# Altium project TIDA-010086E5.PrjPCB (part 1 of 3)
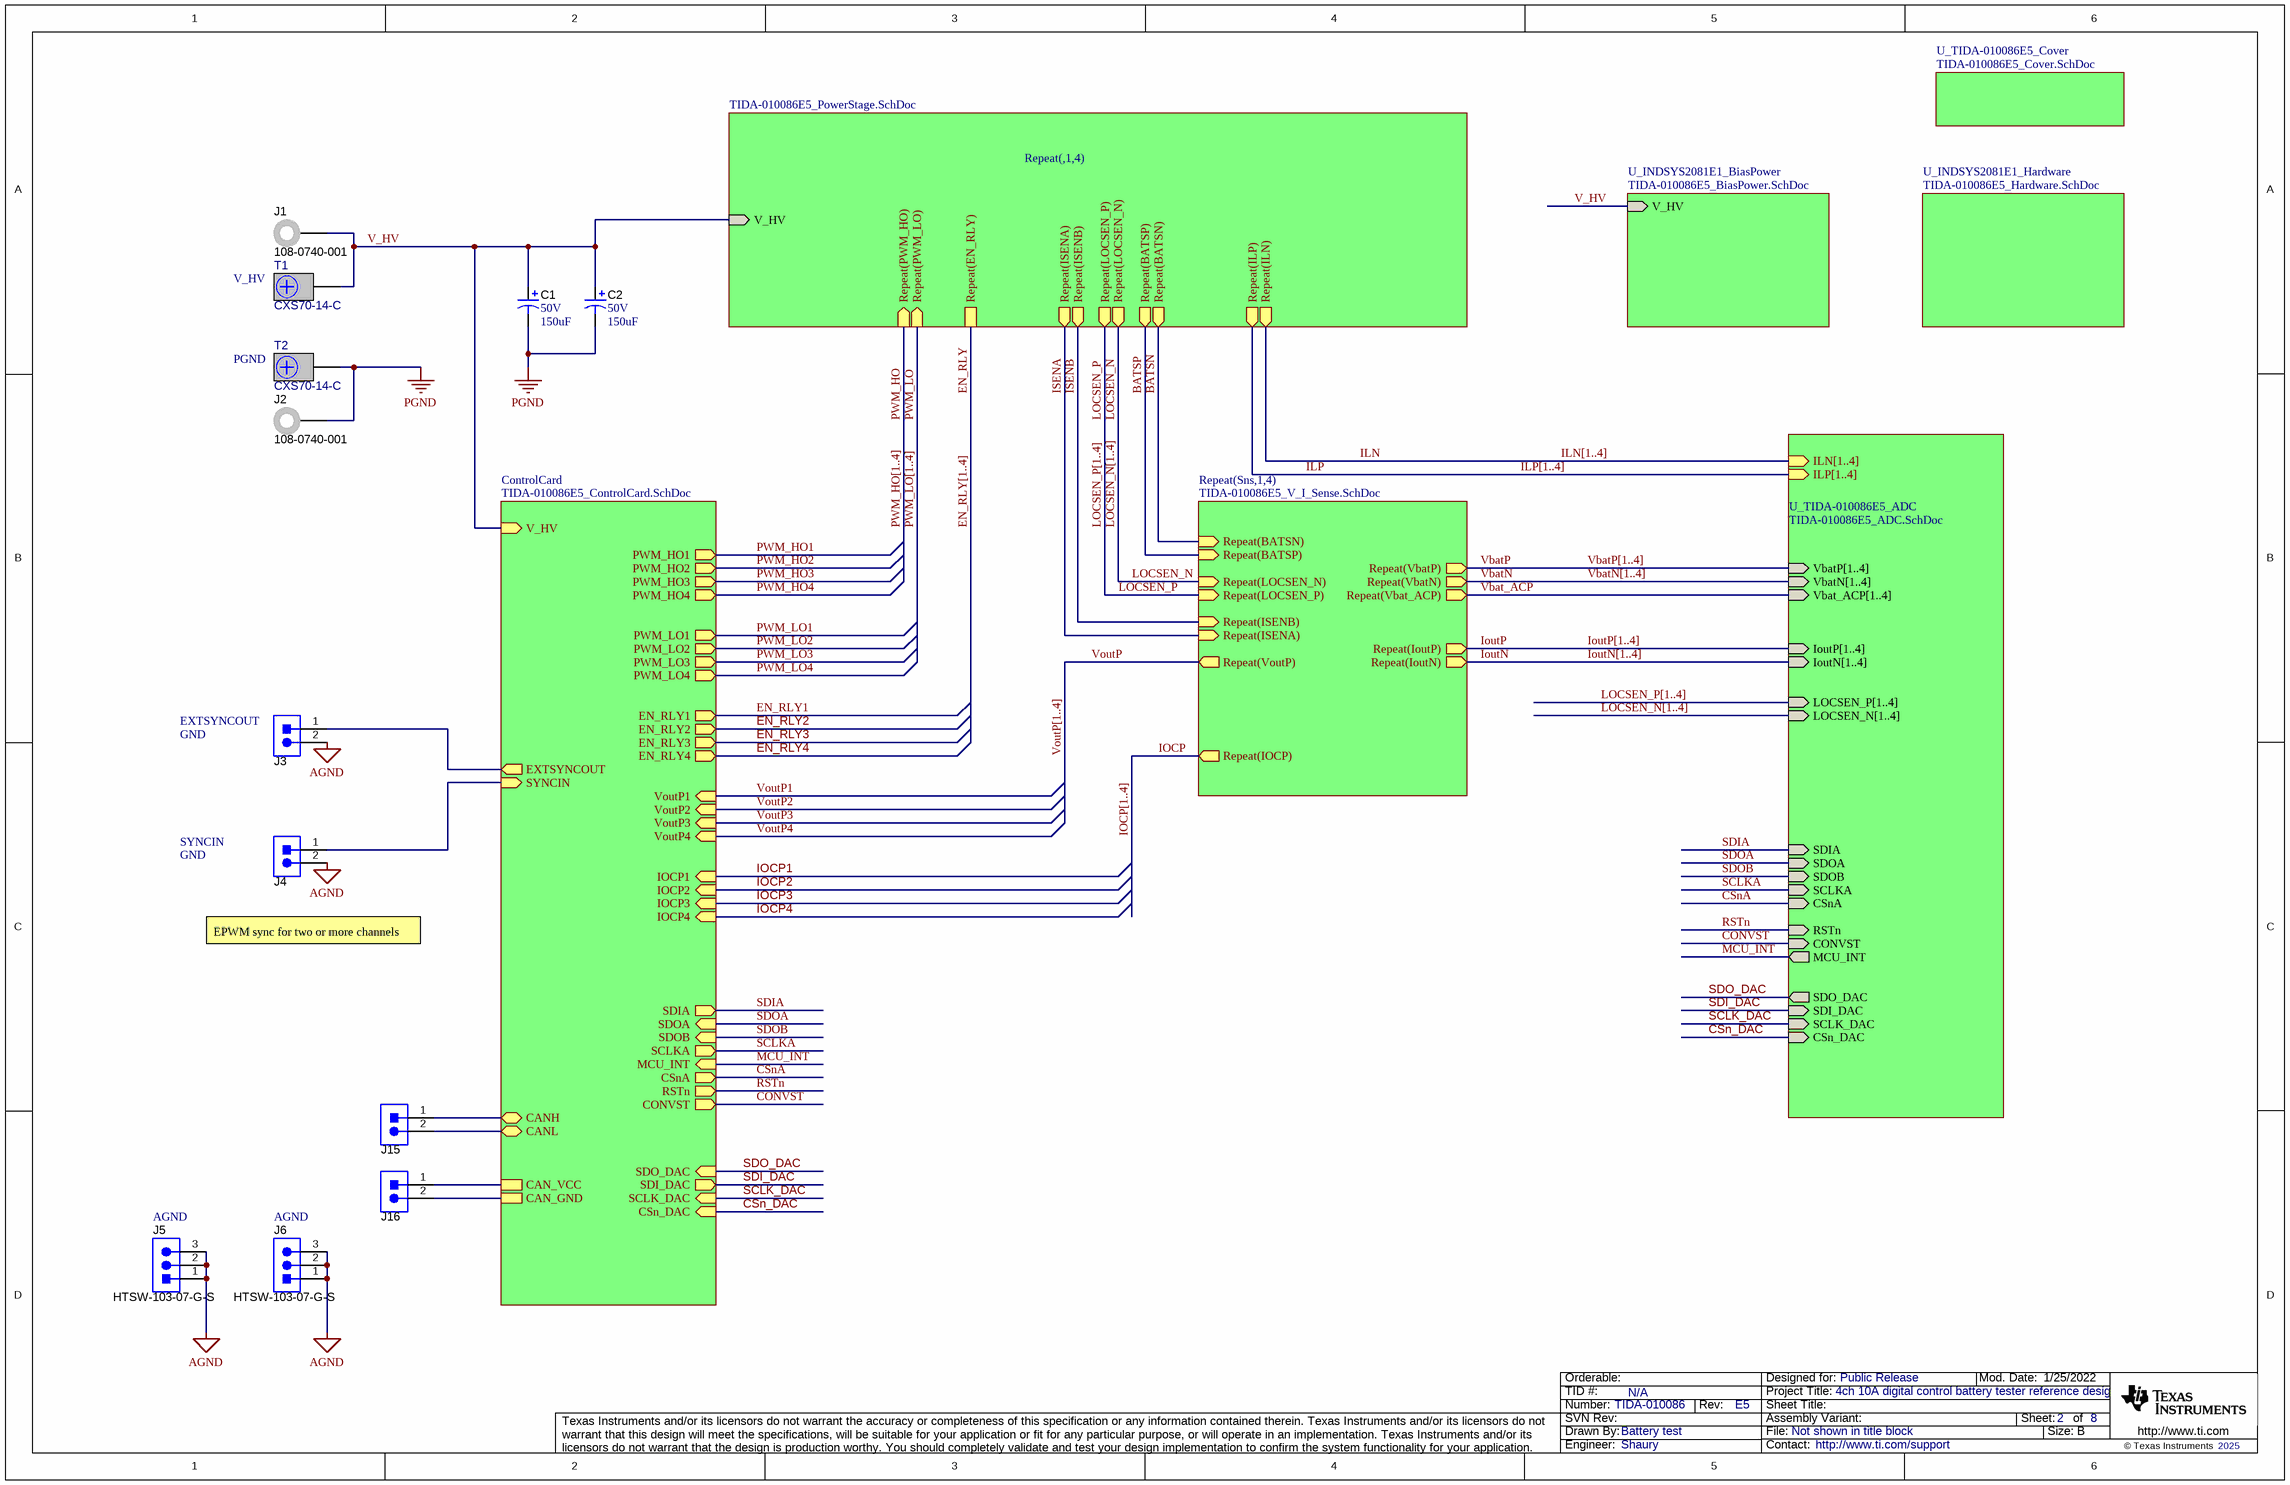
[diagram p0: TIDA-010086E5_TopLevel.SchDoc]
CopyrightYear: 2025; PCB_Layout: Ethan; PCB_Rev: E5; PRJ_Customer: Public Release; PRJ_Engineer: Shaury; PRJ_Number: TIDA-010086; PRJ_Title: 4ch 10A digital control battery tester reference design; SCH_Rev: E5; TechSupport: http://www.ti.com/support; TID: N/A
8 sheets, 718 parts. Net scope: hierarchical (ports join the sheet entries above them; power ports are global).
Board file: TIDA-010086E5.PcbDoc
Sheets:
  TIDA-010086E5_TopLevel.SchDoc
    1 = TIDA-010086E5_PowerStage.SchDoc
    2 = TIDA-010086E5_PowerStage.SchDoc
    3 = TIDA-010086E5_PowerStage.SchDoc
    4 = TIDA-010086E5_PowerStage.SchDoc
    U_INDSYS2081E1_BiasPower = TIDA-010086E5_BiasPower.SchDoc
    ControlCard = TIDA-010086E5_ControlCard.SchDoc
    U_INDSYS2081E1_Hardware = TIDA-010086E5_Hardware.SchDoc
    Sns1 = TIDA-010086E5_V_I_Sense.SchDoc
    Sns2 = TIDA-010086E5_V_I_Sense.SchDoc
    Sns3 = TIDA-010086E5_V_I_Sense.SchDoc
    Sns4 = TIDA-010086E5_V_I_Sense.SchDoc
    U_TIDA-010086E5_ADC = TIDA-010086E5_ADC.SchDoc
    U_TIDA-010086E5_Cover = TIDA-010086E5_Cover.SchDoc

## Sheet TIDA-010086E5_TopLevel.SchDoc
size 431 x 279 mm; Date: Not shown in title block; ApprovedBy: Not shown in title block; CheckedBy: Not shown in title block; Author: Not shown in title block; CompanyName: Not shown in title block; DrawnBy: Battery test; Engineer: Not shown in title block; Organization: Not shown in title block; Address1: Not shown in title block; Address2: Not shown in title block; Address3: Not shown in title block; Address4: Not shown in title block; DocumentNumber: 2; Revision: Use project parameter SCH_Rev; SheetNumber: 2; SheetTotal: 8; PageSetup: Record=PageOptions¦CenterHorizontal=True¦CenterVertical=True¦PrintScale=1.00¦XCorrection=1.00¦YCorrection=1.00¦PrintKind=0¦BorderSize=5000000¦LeftOffset=0¦BottomOffset=0¦Orientation=2¦PaperLength=1000¦PaperWidth=1000¦Scale=100¦PaperSource=15¦PrintQuality=600¦MediaType=1¦DitherType=10¦PaperKind=Letter¦PrintScaleMode=1

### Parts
C1  VDC_V: 50V  ValueDisplayed: 150uF  [CAPSMT_62_F12]  (hidden comment: A768MS157M1HLAE024)
C2  VDC_V: 50V  ValueDisplayed: 150uF  [CAPSMT_62_F12]  (hidden comment: A768MS157M1HLAE024)
J1  108-0740-001  [Johnson_108-0740-001]
J2  108-0740-001  [Johnson_108-0740-001]
J3  B2B-EH-A(LF)(SN)  [JST_B2B-EH-A]  (value not drawn)
J4  B2B-EH-A(LF)(SN)  [JST_B2B-EH-A]  (value not drawn)
J5  HTSW-103-07-G-S  [Samtec_HTSW-103-07-G-S]
J6  HTSW-103-07-G-S  [Samtec_HTSW-103-07-G-S]
J15  B2B-EH-A(LF)(SN)  [JST_B2B-EH-A]  (value not drawn)
J16  B2B-EH-A(LF)(SN)  [JST_B2B-EH-A]  (value not drawn)
T1  CXS70-14-C  [Panduit_CXS70-14-C]
T2  CXS70-14-C  [Panduit_CXS70-14-C]

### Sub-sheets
ControlCard = TIDA-010086E5_ControlCard.SchDoc: PWM_HO1 (out), PWM_LO1 (out), PWM_HO2 (out), PWM_LO2 (out), EXTSYNCOUT (out), SYNCIN (in), VoutP1 (in), VoutP2 (in), VoutP3 (in), VoutP4 (in), PWM_HO3 (out), PWM_LO3 (out), PWM_HO4 (out), PWM_LO4 (out), V_HV (in), SCLKA (out), RSTn (out), IOCP1 (in), IOCP2 (in), IOCP3 (in), IOCP4 (in), EN_RLY1 (out), EN_RLY2 (out), EN_RLY3 (out), EN_RLY4 (out), CONVST (out), MCU_INT (in), SDOA (in), CSnA (out), SDIA (out), SDOB (in), SCLK_DAC (in), CSn_DAC (in), SDI_DAC (out), SDO_DAC (in), CANH (bidir), CANL (bidir), CAN_VCC, CAN_GND
Repeat(,1,4) = TIDA-010086E5_PowerStage.SchDoc: V_HV (in), Repeat(PWM_HO) (in), Repeat(PWM_LO) (in), Repeat(LOCSEN_P) (out), Repeat(LOCSEN_N) (out), Repeat(ISENA) (out), Repeat(ISENB) (out), Repeat(BATSP) (out), Repeat(BATSN) (out), Repeat(EN_RLY), Repeat(ILP) (out), Repeat(ILN) (out)
Repeat(Sns,1,4) = TIDA-010086E5_V_I_Sense.SchDoc: Repeat(IoutP) (out), Repeat(IoutN) (out), Repeat(BATSN) (in), Repeat(BATSP) (in), Repeat(VbatP) (out), Repeat(VbatN) (out), Repeat(LOCSEN_P) (in), Repeat(LOCSEN_N) (in), Repeat(VoutP) (out), Repeat(ISENA) (in), Repeat(ISENB) (in), Repeat(Vbat_ACP) (out), Repeat(IOCP) (out)
U_INDSYS2081E1_BiasPower = TIDA-010086E5_BiasPower.SchDoc: V_HV (in)
U_INDSYS2081E1_Hardware = TIDA-010086E5_Hardware.SchDoc: no entries
U_TIDA-010086E5_ADC = TIDA-010086E5_ADC.SchDoc: SCLKA (in), CSnA (in), CONVST (in), SDIA (in), SDOA (in), RSTn (in), MCU_INT (out), SDOB (in), IoutP[1..4] (in), IoutN[1..4] (in), VbatP[1..4] (in), VbatN[1..4] (in), Vbat_ACP[1..4] (in), LOCSEN_P[1..4] (in), LOCSEN_N[1..4] (in), SCLK_DAC (in), CSn_DAC (in), SDI_DAC (in), SDO_DAC (out), ILP[1..4] (in), ILN[1..4] (in)
U_TIDA-010086E5_Cover = TIDA-010086E5_Cover.SchDoc: no entries

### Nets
AGND: J3.2 J4.2 J5.1 J5.2 J5.3 J6.1 J6.2 J6.3
PGND: C1.2(-) C2.2(-) J2.1 T2.1
BATSN: sheet Repeat(,1,4)/Repeat(BATSN), sheet Repeat(Sns,1,4)/Repeat(BATSN)
BATSP: sheet Repeat(,1,4)/Repeat(BATSP), sheet Repeat(Sns,1,4)/Repeat(BATSP)
CAN_GND: J16.2 ; sheet ControlCard/CAN_GND
CAN_VCC: J16.1 ; sheet ControlCard/CAN_VCC
CANH: J15.1 ; sheet ControlCard/CANH
CANL: J15.2 ; sheet ControlCard/CANL
CONVST: sheet ControlCard/CONVST, sheet U_TIDA-010086E5_ADC/CONVST
CSn_DAC: sheet ControlCard/CSn_DAC, sheet U_TIDA-010086E5_ADC/CSn_DAC
CSnA: sheet ControlCard/CSnA, sheet U_TIDA-010086E5_ADC/CSnA
EXTSYNCOUT: J3.1 ; sheet ControlCard/EXTSYNCOUT
ISENA: sheet Repeat(,1,4)/Repeat(ISENA), sheet Repeat(Sns,1,4)/Repeat(ISENA)
ISENB: sheet Repeat(,1,4)/Repeat(ISENB), sheet Repeat(Sns,1,4)/Repeat(ISENB)
LOCSEN_N: sheet Repeat(,1,4)/Repeat(LOCSEN_N), sheet Repeat(Sns,1,4)/Repeat(LOCSEN_N)
LOCSEN_P: sheet Repeat(,1,4)/Repeat(LOCSEN_P), sheet Repeat(Sns,1,4)/Repeat(LOCSEN_P)
MCU_INT: sheet ControlCard/MCU_INT, sheet U_TIDA-010086E5_ADC/MCU_INT
RSTn: sheet ControlCard/RSTn, sheet U_TIDA-010086E5_ADC/RSTn
SCLK_DAC: sheet ControlCard/SCLK_DAC, sheet U_TIDA-010086E5_ADC/SCLK_DAC
SCLKA: sheet ControlCard/SCLKA, sheet U_TIDA-010086E5_ADC/SCLKA
SDI_DAC: sheet ControlCard/SDI_DAC, sheet U_TIDA-010086E5_ADC/SDI_DAC
SDIA: sheet ControlCard/SDIA, sheet U_TIDA-010086E5_ADC/SDIA
SDO_DAC: sheet ControlCard/SDO_DAC, sheet U_TIDA-010086E5_ADC/SDO_DAC
SDOA: sheet ControlCard/SDOA, sheet U_TIDA-010086E5_ADC/SDOA
SDOB: sheet ControlCard/SDOB, sheet U_TIDA-010086E5_ADC/SDOB
SYNCIN: J4.1 ; sheet ControlCard/SYNCIN
V_HV: C1.1(+) C2.1(+) J1.1 T1.1 ; sheet Repeat(,1,4)/V_HV, sheet U_INDSYS2081E1_BiasPower/V_HV, sheet ControlCard/V_HV

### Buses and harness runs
bus EN_RLY[1..4]
bus ILN[1..4] = sheet U_TIDA-010086E5_ADC/ILN[1..4]
bus ILP[1..4] = sheet U_TIDA-010086E5_ADC/ILP[1..4]
bus IOCP[1..4]
bus IoutN[1..4] = sheet U_TIDA-010086E5_ADC/IoutN[1..4]
bus IoutP[1..4] = sheet U_TIDA-010086E5_ADC/IoutP[1..4]
bus LOCSEN_N[1..4]
bus LOCSEN_N[1..4] = sheet U_TIDA-010086E5_ADC/LOCSEN_N[1..4]
bus LOCSEN_P[1..4]
bus LOCSEN_P[1..4] = sheet U_TIDA-010086E5_ADC/LOCSEN_P[1..4]
bus PWM_HO[1..4]
bus PWM_LO[1..4]
bus VbatN[1..4] = sheet U_TIDA-010086E5_ADC/VbatN[1..4]
bus VbatP[1..4] = sheet U_TIDA-010086E5_ADC/VbatP[1..4]
bus VoutP[1..4]

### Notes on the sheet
- V_HV
- PGND
- EXTSYNCOUT
- GND
- SYNCIN
- EPWM sync for two or more channels
- (near J5) AGND
- (near J6) AGND

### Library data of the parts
C1 C2 = CMP-0012120-3: CAP ALUM POLY 150UF 20% 50V SMD; Manufacturer: Panasonic; TaMin_C: -55°C; ESR_ohm: 24m; Polarized: Y; Value1: 0.024 ohm; TaMax_C: 105°C; SizeZ_mm: 13; SizeX_mm: 10.3; Cap_Case: F12; Value2: 50; CompType: Capacitor; AEC Qualified: N; AEC Category: Q200
J1 J2 = CMP-0055387-2: Standard Banana Jack, Uninsulated, 15A; Manufacturer: Cinch Connectivity; CNHeader: FALSE; Green_Lifecycle: Active; Green_REACh: Passed; CT: TRUE
J3 J4 J15 J16 = CMP-0075228-1: Header (Shrouded), 2.5mm, 2x1, Tin, TH; Manufacturer: JST Manufacturing; Pitch_mm: 2.5; Gender: Male; Shrouded: Y; Row_Count: 1; Current_A: 3A; Voltage_V: 250V; CNHeader: False
J5 J6 = CMP-0075484-1: Header, 100mil, 3x1, Gold, TH; Manufacturer: Samtec; Green_REACh: Passed; CT: False; Green_Lifecycle: Active; CNHeader: True
T1 T2 = CMP-0075010-2: Terminal 70A Lug; Manufacturer: Panduit; CompType: Screw Terminal; CT: False; Green_Lifecycle: Not Set; Green_REACh: Incomplete

## Sheet TIDA-010086E5_PowerStage.SchDoc
size 431 x 279 mm; Date: Not shown in title block; ApprovedBy: Not shown in title block; CheckedBy: Not shown in title block; Author: Not shown in title block; CompanyName: Not shown in title block; DrawnBy: Battery test; Engineer: Not shown in title block; Organization: Not shown in title block; Address1: Not shown in title block; Address2: Not shown in title block; Address3: Not shown in title block; Address4: Not shown in title block; DocumentNumber: 3; Revision: Use project parameter SCH_Rev; SheetNumber: 3; SheetTotal: 8; PageSetup: Record=PageOptions¦CenterHorizontal=True¦CenterVertical=True¦PrintScale=1.00¦XCorrection=1.00¦YCorrection=1.00¦PrintKind=0¦BorderSize=5000000¦LeftOffset=0¦BottomOffset=0¦Orientation=2¦PaperLength=1000¦PaperWidth=1000¦Scale=100¦PaperSource=15¦PrintQuality=600¦MediaType=1¦DitherType=10¦PaperKind=Letter¦PrintScaleMode=1
Used 4 times, as channels 1, 2, 3, 4. Parts and nets are listed once, with the designators drawn on the sheet.
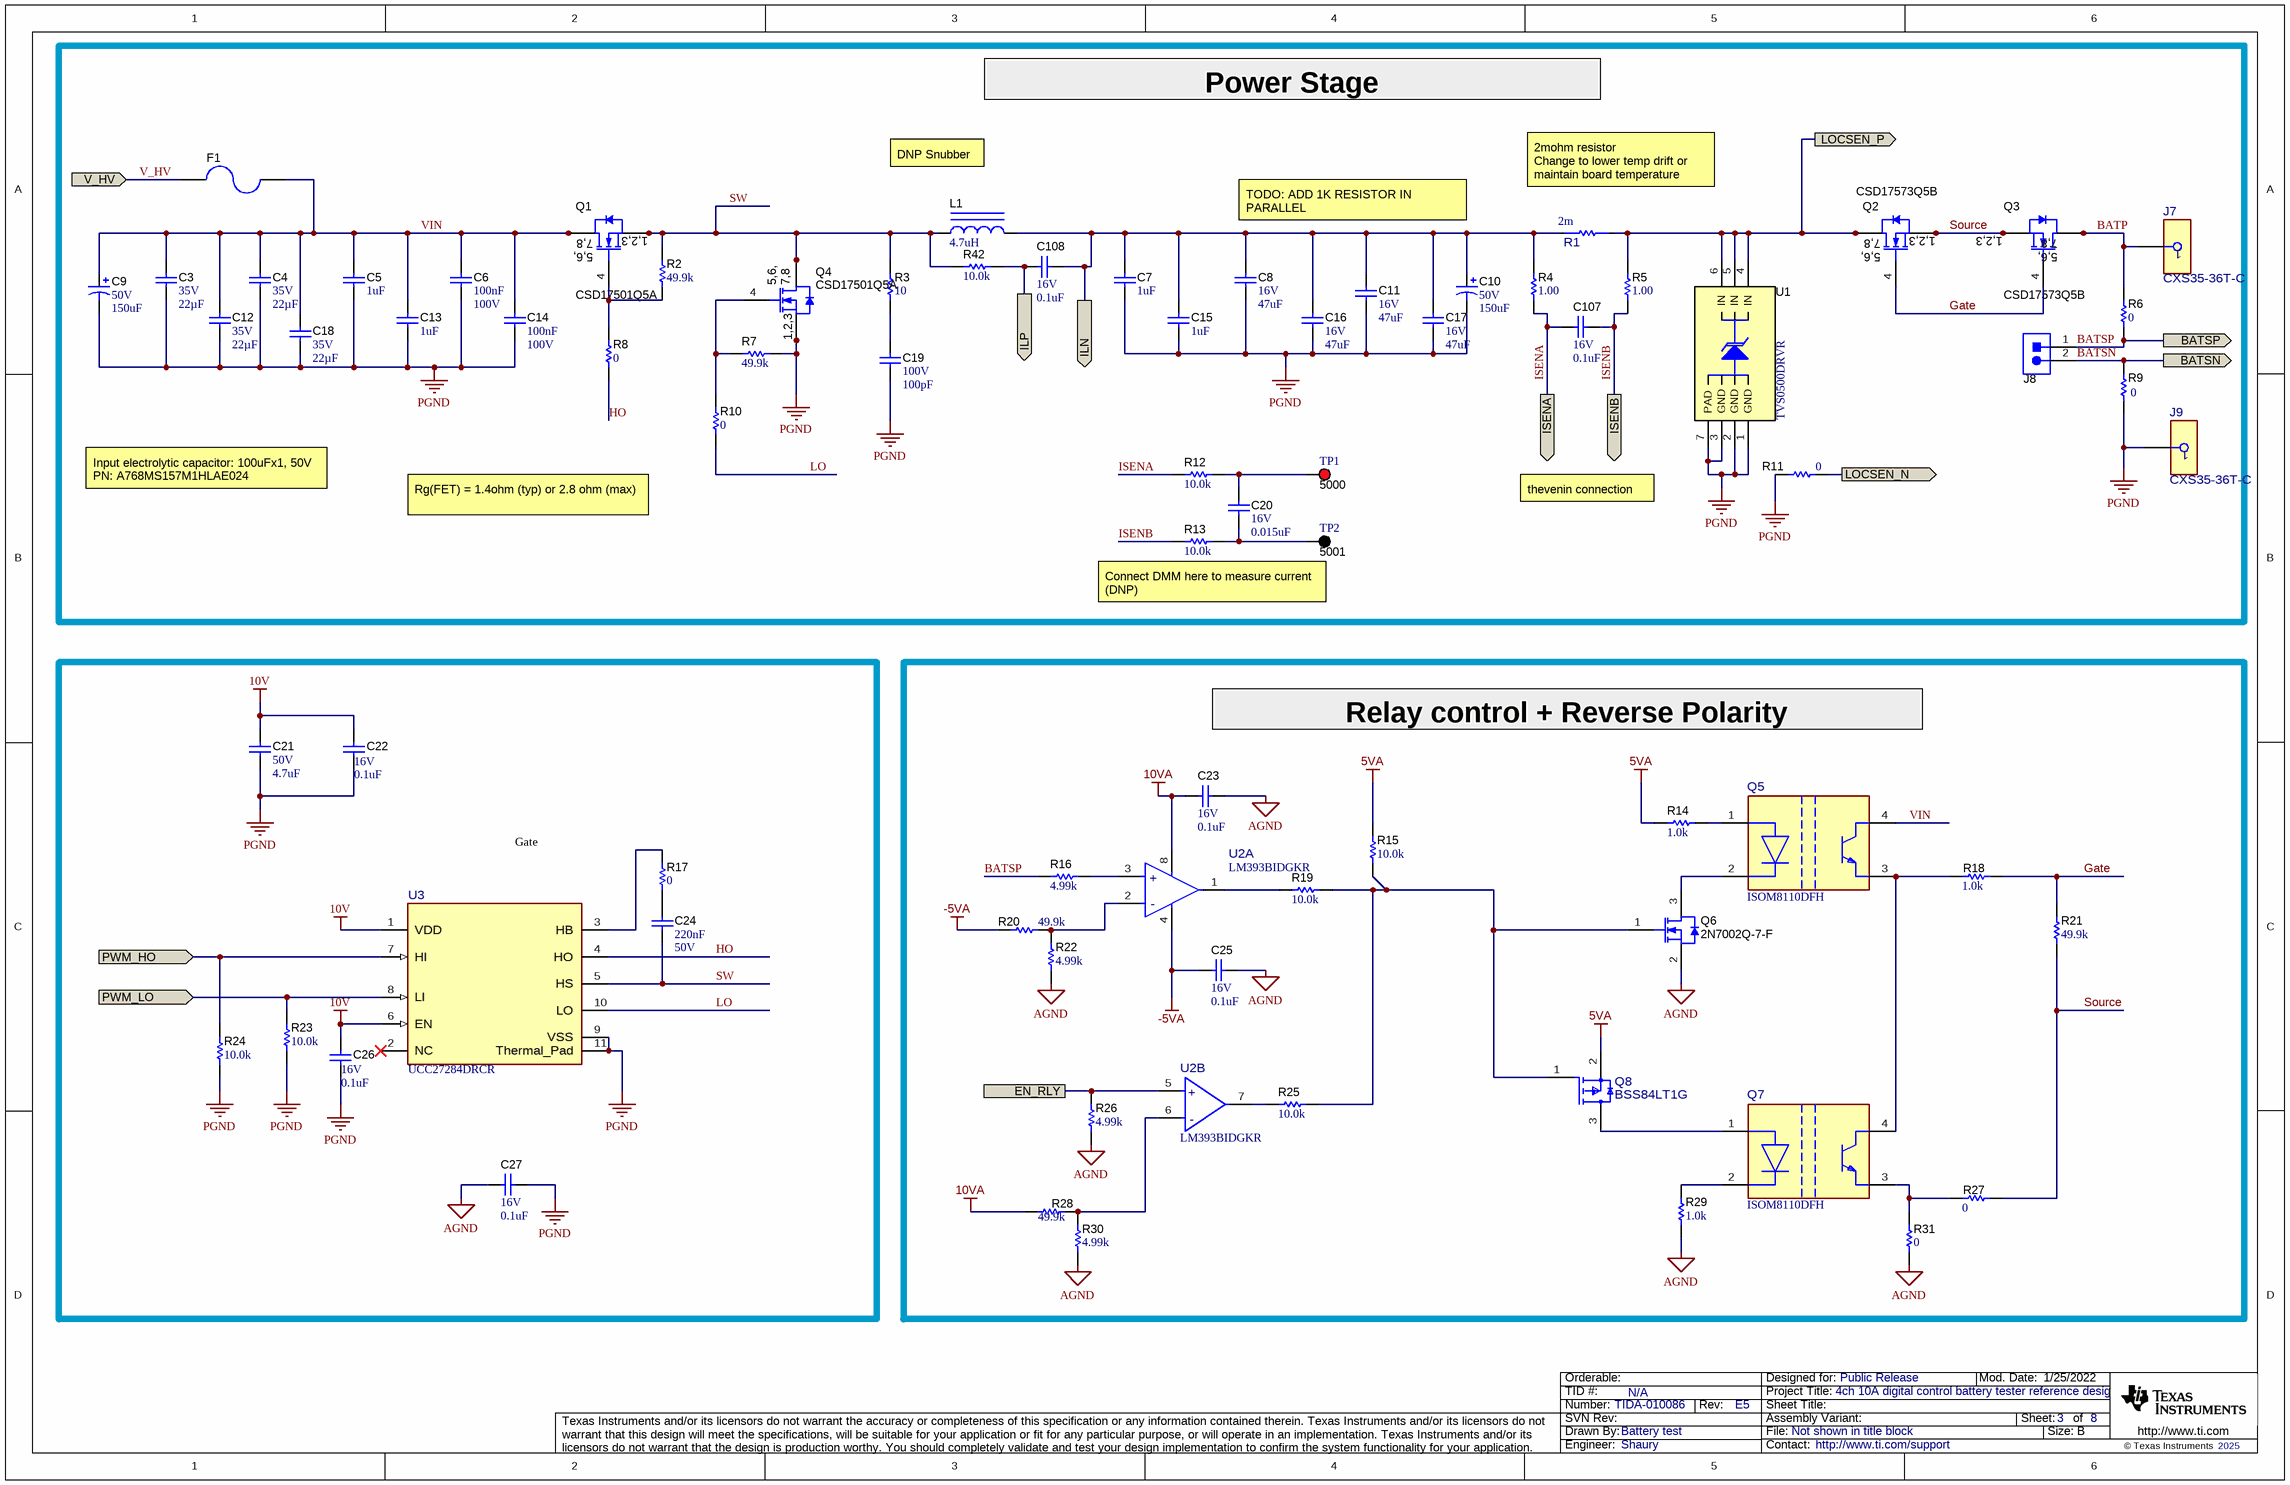
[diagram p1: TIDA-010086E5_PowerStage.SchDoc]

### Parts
C3  VDC_V: 35V  ValueDisplayed: 22µF  [1210]  (hidden comment: GMK325BJ226MM-P)
C4  VDC_V: 35V  ValueDisplayed: 22µF  [1210]  (hidden comment: GMK325BJ226MM-P)
C5  ValueDisplayed: 1uF  [0805_HV]  (hidden comment: GRM21BR71H105KA12L)
C6  Cap_F: 100nF  VDC_V: 100V  [0603]  (hidden comment: GRM188R72A104KA35D)
C7  ValueDisplayed: 1uF  [0805_HV]  (hidden comment: GRM21BR71H105KA12L)
C8  VDC_V: 16V  ValueDisplayed: 47uF  [1210_270]  (hidden comment: GRM32EC81C476ME15L)
C9  VDC_V: 50V  ValueDisplayed: 150uF  [CAPSMT_62_F12]  (hidden comment: A768MS157M1HLAE024)
C10  VDC_V: 50V  ValueDisplayed: 150uF  [CAPSMT_62_F12]  (hidden comment: A768MS157M1HLAE024)
C11  VDC_V: 16V  ValueDisplayed: 47uF  [1210_270]  (hidden comment: GRM32EC81C476ME15L)
C12  VDC_V: 35V  ValueDisplayed: 22µF  [1210]  (hidden comment: GMK325BJ226MM-P)
C13  ValueDisplayed: 1uF  [0805_HV]  (hidden comment: GRM21BR71H105KA12L)
C14  Cap_F: 100nF  VDC_V: 100V  [0603]  (hidden comment: GRM188R72A104KA35D)
C15  ValueDisplayed: 1uF  [0805_HV]  (hidden comment: GRM21BR71H105KA12L)
C16  VDC_V: 16V  ValueDisplayed: 47uF  [1210_270]  (hidden comment: GRM32EC81C476ME15L)
C17  VDC_V: 16V  ValueDisplayed: 47uF  [1210_270]  (hidden comment: GRM32EC81C476ME15L)
C18  VDC_V: 35V  ValueDisplayed: 22µF  [1210]  (hidden comment: GMK325BJ226MM-P)
C19  VDC_V: 100V  ValueDisplayed: 100pF  [0805_HV]  (hidden comment: GRM2165C2A101JA01D)
C20  VDC_V: 16V  ValueDisplayed: 0.015uF  [0402]  (hidden comment: GRM155R71C153KA01D)
C21  VDC_V: 50V  ValueDisplayed: 4.7uF  [0805_HV]  (hidden comment: GRM21BR61H475KE51L)
C22  VDC_V: 16V  ValueDisplayed: 0.1uF  [0402]  (hidden comment: GRM155R61C104KA88D)
C23  VDC_V: 16V  ValueDisplayed: 0.1uF  [0402]  (hidden comment: GRM155R61C104KA88D)
C24  Cap_F: 220nF  VDC_V: 50V  [0603]  (hidden comment: GRM188R71H224KAC4D)
C25  VDC_V: 16V  ValueDisplayed: 0.1uF  [0402]  (hidden comment: GRM155R61C104KA88D)
C26  VDC_V: 16V  ValueDisplayed: 0.1uF  [0402]  (hidden comment: GRM155R61C104KA88D)
C27  VDC_V: 16V  ValueDisplayed: 0.1uF  [0402]  (hidden comment: GRM155R61C104KA88D)
C107  VDC_V: 16V  ValueDisplayed: 0.1uF  [0402]  (hidden comment: GRM155R61C104KA88D)
C108  VDC_V: 16V  ValueDisplayed: 0.1uF  [0402]  (hidden comment: GRM155R71C104JA88D)
F1  CB61F15A-TR1  [6125FA]  (value not drawn)
J7  CXS35-36T-C  [FP-CXS35-36T-C_TERMINAL_LUG-MFG]
J8  B2B-EH-A(LF)(SN)  [JST_B2B-EH-A]  (value not drawn)
J9  CXS35-36T-C  [FP-CXS35-36T-C_TERMINAL_LUG-MFG]
L1  ValueDisplayed: 4.7uH  [XAL1010]  (hidden comment: XAL1010-472MEB)
Q1  CSD17501Q5A  [DQJ0008A]
Q2  CSD17573Q5B  [DNK0008A]
Q3  CSD17573Q5B  [DNK0008A]
Q4  CSD17501Q5A  [DQJ0008A]
Q5  ISOM8110DFH  [DFH0004A-MFG]
Q6  2N7002Q-7-F  [SOT-23]
Q7  ISOM8110DFH  [DFH0004A-MFG]
Q8  BSS84LT1G  [FP-BSS84LT1G_SOT-23-3-318-08-MFG]
R1  Res_ohm: 2m  [FP-SEWF3920F2L00P9_3920-MFG]  (hidden comment: SEWF3920F2L00P9)
R2  ValueDisplayed: 49.9k  [0603]  (hidden comment: CRCW060349K9FKEA)
R3  ValueDisplayed: 10  [0805_HV]  (hidden comment: CRCW080510R0JNEA)
R4  ValueDisplayed: 1.00  [0603]  (hidden comment: CRCW06031R00FKEA)
R5  ValueDisplayed: 1.00  [0603]  (hidden comment: CRCW06031R00FKEA)
R6  ValueDisplayed: 0  [0402]  (hidden comment: CRCW04020000Z0ED)
R7  ValueDisplayed: 49.9k  [0603]  (hidden comment: CRCW060349K9FKEA)
R8  ValueDisplayed: 0  [0402]  (hidden comment: CRCW04020000Z0ED)
R9  ValueDisplayed: 0  [0402]  (hidden comment: CRCW04020000Z0ED)
R10  ValueDisplayed: 0  [0402]  (hidden comment: CRCW04020000Z0ED)
R11  ValueDisplayed: 0  [0402]  (hidden comment: CRCW04020000Z0ED)
R12  ValueDisplayed: 10.0k  [0603]  (hidden comment: CRCW060310K0FKEA)
R13  ValueDisplayed: 10.0k  [0603]  (hidden comment: CRCW060310K0FKEA)
R14  ValueDisplayed: 1.0k  [0603]  (hidden comment: CRCW06031K00JNEA)
R15  ValueDisplayed: 10.0k  [0603]  (hidden comment: CRCW060310K0FKEA)
R16  ValueDisplayed: 4.99k  [0603]  (hidden comment: CRCW06034K99FKEAC)
R17  ValueDisplayed: 0  [0402]  (hidden comment: CRCW04020000Z0ED)
R18  ValueDisplayed: 1.0k  [0603]  (hidden comment: CRCW06031K00JNEA)
R19  ValueDisplayed: 10.0k  [0603]  (hidden comment: CRCW060310K0FKEA)
R20  ValueDisplayed: 49.9k  [0603]  (hidden comment: CRCW060349K9FKEA)
R21  ValueDisplayed: 49.9k  [0603]  (hidden comment: CRCW060349K9FKEA)
R22  ValueDisplayed: 4.99k  [0603]  (hidden comment: CRCW06034K99FKEAC)
R23  ValueDisplayed: 10.0k  [0603]  (hidden comment: CRCW060310K0FKEA)
R24  ValueDisplayed: 10.0k  [0603]  (hidden comment: CRCW060310K0FKEA)
R25  ValueDisplayed: 10.0k  [0603]  (hidden comment: CRCW060310K0FKEA)
R26  ValueDisplayed: 4.99k  [0603]  (hidden comment: CRCW06034K99FKEAC)
R27  ValueDisplayed: 0  [0402]  (hidden comment: CRCW04020000Z0ED)
R28  ValueDisplayed: 49.9k  [0603]  (hidden comment: CRCW060349K9FKEA)
R29  ValueDisplayed: 1.0k  [0603]  (hidden comment: CRCW06031K00JNEA)
R30  ValueDisplayed: 4.99k  [0603]  (hidden comment: CRCW06034K99FKEAC)
R31  ValueDisplayed: 0  [0402]  (hidden comment: CRCW04020000Z0ED)
R42  ValueDisplayed: 10.0k  [0603]  (hidden comment: CRCW060310K0FKEA)
TP1  5000  [Keystone5000]
TP2  5001  [Keystone5001]
U1  TVS0500DRVR  [DRV0006A]
U2  LM393BIDGKR  [DGK0008A-MFG]  (parts A,B of 2)
U3  UCC27284DRCR  [DRC0010J-MFG]

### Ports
BATSN (out), BATSP (out), EN_RLY, ILN (out), ILP (out), ISENA (out), ISENB (out), LOCSEN_N (out), LOCSEN_P (out), PWM_HO (in), PWM_LO (in), V_HV (in)

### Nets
5VA: Q8.2(S) R14.2 R15.2
10V: C21.1 C22.2 C26.2 U3.1(VDD) U3.6(EN)
10VA: C23.1 R28.2 U2.8(VCC)
-5VA: C25.1 R20.2 U2.4(GND)
AGND: C23.2 C25.2 C27.1 Q6.2(S) R22.1 R26.1 R29.2 R30.1 R31.2
PGND: C3.2 C4.2 C5.2 C6.2 C7.2 C8.2 C9.2(-) C10.2(-) C11.2 C12.2 C13.2 C14.2 C15.2 C16.2 C17.2 C18.2 C19.2 C21.2 C22.1 C26.1 C27.2 J9.1 Q4.1(S) Q4.2(S) Q4.3(S) R7.1 R9.1 R11.1 R23.1 R24.1 U1.1(GND) U1.2(GND) U1.3(GND) U1.7(PAD) U3.9(VSS) U3.11(Thermal_Pad)
BATP: J7.1 Q3.5(D) Q3.6(D) Q3.7(D) Q3.8(D) Q3.9(D) R6.1
BATSN: J8.2 R9.2 ; port BATSN
BATSP: J8.1 R6.2 R16.2 ; port BATSP
EN_RLY: R26.2 U2.5(2IN+) ; port EN_RLY
Gate: Q2.4(G) Q3.4(G) R18.1 R21.1
HO: R8.1 U3.4(HO)
ILN: C7.1 C8.1 C10.1(+) C11.1 C15.1 C16.1 C17.1 C108.2 L1.2 R1.1 R4.2 ; port ILN
ILP: C108.1 R42.1 ; port ILP
ISENA: C107.1 R4.1 R12.2 ; port ISENA
ISENB: C107.2 R5.1 R13.2 ; port ISENB
LO: R10.1 U3.10(LO)
LOCSEN_N: R11.2 ; port LOCSEN_N
LOCSEN_P: Q2.5(D) Q2.6(D) Q2.7(D) Q2.8(D) Q2.9(D) R1.2 R5.2 U1.4(IN) U1.5(IN) U1.6(IN) ; port LOCSEN_P
PWM_HO: R24.2 U3.7(HI) ; port PWM_HO
PWM_LO: R23.2 U3.8(LI) ; port PWM_LO
Source: Q2.1(S) Q2.2(S) Q2.3(S) Q3.1(S) Q3.2(S) Q3.3(S) R21.2 R27.1
SW: C24.2 L1.1 Q1.1(S) Q1.2(S) Q1.3(S) Q4.5(D) Q4.6(D) Q4.7(D) Q4.8(D) Q4.9(D) R2.2 R3.2 R42.2 U3.5(HS)
V_HV: F1.2 ; port V_HV
VIN: C3.1 C4.1 C5.1 C6.1 C9.1(+) C12.1 C13.1 C14.1 C18.1 F1.1 Q1.5(D) Q1.6(D) Q1.7(D) Q1.8(D) Q1.9(D) Q5.4(COL)
NetC19_1: C19.1 R3.1
NetC20_1: C20.1 R12.1 TP1.1
NetC20_2: C20.2 R13.1 TP2.1
NetC24_1: C24.1 R17.1
NetQ1_4: Q1.4(G) R2.1 R8.2
NetQ4_4: Q4.4(G) R7.2 R10.2
NetQ5_1: Q5.1(AN) R14.1
NetQ5_2: Q5.2(CAT) Q6.3(D)
NetQ5_3: Q5.3(EM) Q7.4(COL) R18.2
NetQ6_1: Q6.1(G) Q8.1(G) R15.1 R19.1 R25.1
NetQ7_1: Q7.1(AN) Q8.3(D)
NetQ7_2: Q7.2(CAT) R29.1
NetQ7_3: Q7.3(EM) R27.2 R31.1
NetR16_1: R16.1 U2.3(1IN+)
NetR17_2: R17.2 U3.3(HB)
NetR19_2: R19.2 U2.1(1OUT)
NetR20_1: R20.1 R22.2 U2.2(1IN-)
NetR25_2: R25.2 U2.7(2OUT)
NetR28_1: R28.1 R30.2 U2.6(2IN-)

Not connected (* = marked no-connect by the designer): U3 2(NC)*

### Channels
1: designators end in _1; ports BATSN=BATSN1 BATSP=BATSP1 EN_RLY=EN_RLY1 ILN=ILN1 ILP=ILP1 ISENA=ISENA1 ISENB=ISENB1 LOCSEN_N=LOCSEN_N1 LOCSEN_P=LOCSEN_P1 PWM_HO=PWM_HO1 PWM_LO=PWM_LO1 V_HV=V_HV
2: designators end in _2; ports BATSN=BATSN2 BATSP=BATSP2 EN_RLY=EN_RLY2 ILN=ILN2 ILP=ILP2 ISENA=ISENA2 ISENB=ISENB2 LOCSEN_N=LOCSEN_N2 LOCSEN_P=LOCSEN_P2 PWM_HO=PWM_HO2 PWM_LO=PWM_LO2 V_HV=V_HV
3: designators end in _3; ports BATSN=BATSN3 BATSP=BATSP3 EN_RLY=EN_RLY3 ILN=ILN3 ILP=ILP3 ISENA=ISENA3 ISENB=ISENB3 LOCSEN_N=LOCSEN_N3 LOCSEN_P=LOCSEN_P3 PWM_HO=PWM_HO3 PWM_LO=PWM_LO3 V_HV=V_HV
4: designators end in _4; ports BATSN=BATSN4 BATSP=BATSP4 EN_RLY=EN_RLY4 ILN=ILN4 ILP=ILP4 ISENA=ISENA4 ISENB=ISENB4 LOCSEN_N=LOCSEN_N4 LOCSEN_P=LOCSEN_P4 PWM_HO=PWM_HO4 PWM_LO=PWM_LO4 V_HV=V_HV

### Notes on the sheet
- Power Stage
- DNP Snubber
- TODO: ADD 1K RESISTOR IN PARALLEL
- (near R1) 2mohm resistor
  Change to lower temp drift or maintain board temperature
- Input electrolytic capacitor: 100uFx1, 50V
  PN: A768MS157M1HLAE024
- thevenin connection
- Rg(FET) = 1.4ohm (typ) or 2.8 ohm (max)
- Connect DMM here to measure current
  (DNP)
- Relay control + Reverse Polarity
- Gate driver

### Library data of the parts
C3 C4 C12 C18 = CMP-0085817-1: CAP, CERM, 22 µF, 35 V,+/- 20%, X5R, 1210; Manufacturer: Taiyo Yuden; Value: 22uF; SizeZ_mm: 1.35; TaMax_C: 85°C; U/M: EA; SizeAreaWB_mm2: 14.7; SizeX_mm: 3.2; SizeArea_mm2: 8; TaMin_C: -55°C; AEC Qualified: N; SizeY_mm: 2.5; AEC Category: Q200
C5 C7 C13 C15 = CMP-0008350-2: CAP, CERM, 1 uF, 50 V, +/- 10%, X7R, 0805; Manufacturer: MuRata; Polarized: N; Value: 1uF; U/M: EA; Cap_F: 1µF; Value1: Unknown; VDC_V: 50V; TaMin_C: -55°C; TaMax_C: 125°C; Cap_Case: 0805; AEC Category: Q200; SizeArea_mm2: 2.5; SizeAreaWB_mm2: 6.75; SizeX_mm: 2; SizeY_mm: 1.25; SizeZ_mm: 1.45
C6 C14 = CMP-0007469-4: CAP, CERM, 0.1 uF, 100 V, +/- 10%, X7R, 0603; Manufacturer: MuRata; TaMin_C: -55°C; Polarized: N; SizeAreaWB_mm2: 4.68; Value1: Unknown; U/M: EA; Value: 0.1uF; TaMax_C: 125°C; SizeZ_mm: 1; SizeX_mm: 1.6; SizeY_mm: 0.8; SizeArea_mm2: 1.28; AEC Category: Q200
C8 C11 C16 C17 = CMP-0009201-2: CAP, CERM, 47 uF, 16 V, +/- 20%, X6S, 1210; Manufacturer: MuRata; TaMin_C: -55°C; Polarized: N; SizeAreaWB_mm2: 14.7; Value1: Unknown; U/M: EA; Value: 47uF; TaMax_C: 105°C; SizeZ_mm: 2.7; SizeX_mm: 3.2; SizeY_mm: 2.5; Cap_Case: 1210; SizeArea_mm2: 8; Cap_F: 47µF; AEC Category: Q200
C9 C10 = CMP-0012120-3: as C1 on sheet TIDA-010086E5_TopLevel
C19 = CMP-0008093-2: CAP, CERM, 100 pF, 100 V, +/- 5%, C0G/NP0, 0805; Manufacturer: MuRata; TaMin_C: -55°C; Polarized: N; SizeAreaWB_mm2: 6.75; Value1: Unknown; U/M: EA; Value: 100pF; TaMax_C: 125°C; SizeZ_mm: 1.45; SizeX_mm: 2; SizeY_mm: 1.25; Cap_Case: 0805; SizeArea_mm2: 2.5; AEC Category: Q200
C20 = CMP-0006644-2: CAP, CERM, 0.015 uF, 16 V, +/- 10%, X7R, 0402; Manufacturer: MuRata; TaMin_C: -55°C; Polarized: N; SizeAreaWB_mm2: 3; Value1: Unknown; U/M: EA; TaMax_C: 125°C; SizeZ_mm: 0.6; SizeX_mm: 1; SizeY_mm: 0.5; Cap_F: 15nF; AEC Category: Q200
C21 = CMP-0008309-2: CAP, CERM, 4.7 uF, 50 V, +/- 10%, X5R, 0805; Manufacturer: MuRata; TaMin_C: -55°C; Polarized: N; SizeAreaWB_mm2: 6.75; Value1: Unknown; U/M: EA; Value: 4.7uF; TaMax_C: 85°C; SizeZ_mm: 1.45; SizeX_mm: 2; SizeY_mm: 1.25; Cap_Case: 0805; SizeArea_mm2: 2.5; Cap_F: 4.7µF; AEC Category: Q200
C22 C23 C25-C27 C107 = CMP-0006591-2: CAP, CERM, 0.1 uF, 16 V, +/- 10%, X5R, 0402; Manufacturer: MuRata; TaMin_C: -55°C; Polarized: N; SizeAreaWB_mm2: 3; Value1: Unknown; U/M: EA; Value: 0.1uF; TaMax_C: 85°C; SizeZ_mm: 0.6; SizeX_mm: 1; SizeY_mm: 0.5; Cap_F: 100nF; AEC Category: Q200
C24 = CMP-0007445-4: CAP, CERM, 0.22 uF, 50 V, +/- 10%, X7R, 0603; Manufacturer: MuRata; TaMin_C: -55°C; Polarized: N; SizeAreaWB_mm2: 4.68; Value1: Unknown; U/M: EA; Value: 0.22uF; TaMax_C: 125°C; SizeZ_mm: 1; SizeX_mm: 1.6; SizeY_mm: 0.8; SizeArea_mm2: 1.28; AEC Category: Q200
C108 = CMP-0006640-1: CAP, CERM, 0.1 uF, 16 V, +/- 5%, X7R, 0402; Manufacturer: MuRata; TaMin_C: -55°C; Polarized: N; SizeAreaWB_mm2: 3; Value1: Unknown; U/M: EA; Value: 0.1uF; TaMax_C: 125°C; SizeZ_mm: 0.6; SizeX_mm: 1; SizeY_mm: 0.5; Cap_F: 100nF; AEC Category: Q200
F1 = CMP-0003569-2: Fuse, 15 A, SMD; Irating_A: 15A; Rtyp_Ohm: 4m
J7 J9 = CMP-0001389-1: Terminal Connector Rectangular Lug, Grounding 6-14 AWG 3/16 Stud; Manufacturer: Panduit; ContactFinish: Tin; Voltage_V: 600V; AEC Qualified: No; Conn Gender: Female; Conn Orientation: Horizontal; Is Female: yes; Max Wire Gauge: 6; Min Wire Gauge: 14
J8 = CMP-0075228-1: as J3 on sheet TIDA-010086E5_TopLevel
L1 = CMP-0060950-1: Inductor, Shielded, Composite, 4.7 uH, 24 A, 0.01 ohm, SMD; Manufacturer: Coilcraft; Isat: 25.4A @ 30% inductance drop; Green_Lifecycle: Not Set; SizeAreaWB_mm2: 159.6; DCR_ohm: 10m; Green_REACh: Incomplete; Irms: 24A @ 40C rise; Value: 4.7uH; Imax_A: 24A; SizeZ_mm: 10; SizeX_mm: 11.3; SizeArea_mm2: 113; Ind_H: 4.7µH; AEC Category: Q200
Q1 Q4 = CMP-0000572-1: MOSFET, N-CH, 30 V, 100 A, DQJ0008A (VSONP-8); Alternate Manufacturer: None; Manufacturer: Texas Instruments; SizeZ_mm: 1.1; ChType: N; Value2: 13.2 nC; Value1: 0; VdsMax_V: 30V; SizeX_mm: 6; SizeY_mm: 4.9; Vgs_V: 20V; Value: 30V; Rdson45_ohm: 3m; SizeArea_mm2: 29.4; AEC Category: Q101; IdsMax_A: 100A; SizeAreaWB_mm2: 55.2; U/M: EA; QgTyp_nC: 13.2
Q2 Q3 = CMP-0000586-2: MOSFET, N-CH, 30 V, 100 A, DNK0008A (VSON-CLIP-8); Alternate Manufacturer: None; Manufacturer: Texas Instruments; SizeZ_mm: 1; ChType: N; Value2: 49 nC; Value1: 0.0014; VdsMax_V: 30V; SizeX_mm: 6; SizeY_mm: 5; Vgs_V: 20V; Value: 30V; Rdson45_ohm: 1.45m; SizeArea_mm2: 30; AEC Category: Q101; IdsMax_A: 100A; SizeAreaWB_mm2: 56; U/M: EA; QgTyp_nC: 49
Q5 Q7 = CMP-0120549-1: 3.75-kVRMS, Single-Channel Opto-Emulator with Analog Transistor Output; Manufacturer: Texas Instruments; SizeZ_mm: 2.65mm; AEC Qualified: No; CTR (Max): 195%; CTR (Min): 55%; Emiiter Collector Voltage: 7V; Forward Current: 5mA; Power_TotalModule: 200mW; Standoff Height: 0.05mm; TaMax_C: +125°C; TaMin_C: -55°C; TJmax_C: +150°C; Turn Off Delay Time: 5.7us; Turn On Delay Time: 3.6us; Value: 80V; Vf_V: 1.2V; Voltage_Isolation_Vrms: 3750Vrms
Q6 = CMP-0085603-1: MOSFET, N-CH, 60 V, 0.115 A, AEC-Q101, SOT-23; Manufacturer: Diodes Inc.; Alternate Manufacturer: None; SizeAreaWB_mm2: 14; Value: 60V; QgTyp_nC: 0.223; IdsMax_A: 115mA; AEC Category: Q101; SizeY_mm: 3; SizeArea_mm2: 7.5; SizeX_mm: 2.5; SizeZ_mm: 1.1; Value1: ? ohm; ChMode: Enhancement; Vgs_V: 20V; ChType: N; AEC Qualified: Y; Value2: 0.223 nC
Q8 = CMP-0090761-1: P-Channel 50V 130mA (Ta) 225mW (Ta) Surface Mount SOT-23-3 (TO-236); Manufacturer: On Semiconductor; IdsMax_A: -130mA; Number Of Channels: 1; Rthja Max: 556°C/W; Standoff Height: 0.01mm; Threshold Vgs Max: -2V; TJmax_C: +150°C; Pulse Drain Current: -520mA; Import Ts: 1521845730; VdsMax_V: -2.2V; Turn On Delay Time: 3.6ns; QgTyp_nC: 2.2nC @ -10V; Input Capacitace At Vds: 36pF @ 5V; Drain To Source Breakdown Voltage: -50V; Rdson45_ohm: 4.7; ChMode: False; AEC Qualified: No; Threshold Vgs Min: -0.9V; SizeZ_mm: 1.11mm; Ciiva Ids: 12912405; Vgs_V: 20V; Turn Off Delay Time: 12ns
R1 = CMP-0042997-1: 2 mOhms ±1% 6W Chip Resistor 3920 (1052 Metric) Automotive AEC-Q200, Current Sense Metal Element; Manufacturer: RESI; AEC Grade: Grade 0; AEC Qualified: Yes; SizeZ_mm: 1.35mm; TempCo: 25ppm/°C; Value: 2m
R2 R7 R20 R21 R28 = CMP-0022447-4: RES, 49.9 k, 1%, 0.1 W, AEC-Q200 Grade 0, 0603; Manufacturer: Vishay-Dale; Power_W: 100mW; TempCo: 100 ppm/C; Value_Code: 49k9; Value: 49.9k; EIA_Code: E96; SizeX_mm: 1.6; SizeY_mm: 0.8; SizeZ_mm: 1; Value2: 0.1W; SizeArea_mm2: 1.28; AEC Qualified: Y; VDC_V: 75V; AEC Category: Q200; AEC Grade: 0
R3 = CMP-0020448-3: RES, 10, 5%, 0.125 W, AEC-Q200 Grade 0, 0805; Manufacturer: Vishay-Dale; Power_W: 125mW; TempCo: 200 ppm/C; Value_Code: 10R0; Value: 10; EIA_Code: E24; SizeX_mm: 2; SizeY_mm: 1.25; SizeZ_mm: 1.45; Value2: 0.125W; SizeArea_mm2: 2.5; AEC Qualified: Y; VDC_V: 150V; AEC Category: Q200; AEC Grade: 0
R4 R5 = CMP-0022170-4: RES, 1.00, 1%, 0.1 W, AEC-Q200 Grade 0, 0603; Manufacturer: Vishay-Dale; Power_W: 100mW; TempCo: 100 ppm/C; Value_Code: 1R00; Value: 1.00; EIA_Code: E96; Res_ohm: 1; SizeX_mm: 1.6; SizeY_mm: 0.8; Value2: 0.1W; SizeArea_mm2: 1.28; AEC Qualified: Y; VDC_V: 75V; AEC Category: Q200; AEC Grade: 0
R6 R8-R11 R17 R27 R31 = CMP-0026822-3: RES, 0, 5%, 0.063 W, AEC-Q200 Grade 0, 0402; Manufacturer: Vishay-Dale; Value: 0; Value_Code: 0000; Power_W: 63mW; Value2: 0.063W; VDC_V: 50V; TempCo: 200 ppm/C; SizeArea_mm2: 0.5; SizeX_mm: 1; SizeZ_mm: 0.6; EIA_Code: E24; AEC Category: Q200; AEC Qualified: Y
R12 R13 R15 R19 R23-R25 R42 = CMP-0021998-4: RES, 10.0 k, 1%, 0.1 W, AEC-Q200 Grade 0, 0603; Manufacturer: Vishay-Dale; Power_W: 100mW; TempCo: 100 ppm/C; Value_Code: 10k0; Value: 10.0k; EIA_Code: E96; Res_ohm: 10k; SizeX_mm: 1.6; SizeY_mm: 0.8; SizeZ_mm: 1; Value2: 0.1W; SizeArea_mm2: 1.28; AEC Qualified: Y; VDC_V: 75V; AEC Category: Q200; AEC Grade: 0
R14 R18 R29 = CMP-0025729-4: RES, 1.0 k, 5%, 0.1 W, AEC-Q200 Grade 0, 0603; Manufacturer: Vishay-Dale; Power_W: 100mW; TempCo: 200 ppm/C; Value_Code: 1k00; Value: 1.0k; EIA_Code: E24; Res_ohm: 1k; SizeX_mm: 1.6; SizeY_mm: 0.8; SizeZ_mm: 1; Value2: 0.1W; SizeArea_mm2: 1.28; AEC Qualified: Y; VDC_V: 75V; AEC Category: Q200; AEC Grade: 0
R16 R22 R26 R30 = CMP-0082533-1: RES, 4.99 k, 1%, 0.1 W, 0603; Manufacturer: Vishay-Dale; Power_W: 100mW; TempCo: 100 ppm/C; SizeAreaWB_mm2: 4.68; Value_Code: 4k99; Value: 4.99k; EIA_Code: E96; SizeX_mm: 1.6; SizeY_mm: 0.8; SizeZ_mm: 1; Value2: 0.1W; SizeArea_mm2: 1.28; AEC Qualified: N; VDC_V: 75V; AEC Category: Q200
TP1 = CMP-0055137-2: Test Point, Miniature, Red, TH; Manufacturer: Keystone Electronics; Green_REACh: Passed; Green_Lifecycle: Active; ContactFinish: Silver; CNHeader: FALSE; CT: TRUE
TP2 = CMP-0055138-2: Test Point, Miniature, Black, TH; Manufacturer: Keystone Electronics; ContactFinish: Silver; CNHeader: FALSE; Green_Lifecycle: Active; Green_REACh: Passed; CT: TRUE
U1 = CMP-0077837-1: 5-V Precision Surge Protection Clamp, DRV0006A (WSON-6); Alternate Manufacturer: Texas Instruments; SizeAreaWB_mm2: 9.0; SizeZ_mm: 0.8; SizeX_mm: 2.0; SizeArea_mm2: 4.0; CompType: IC; AEC Qualified: N; AEC Category: Q200
U2 = CMP-0089361-1: Dual Comparators; Manufacturer: Texas Instruments; TaMin_C: -40°C; Nominal Supply Current: 400-550uA; Min Supply Voltage: 3V; TaMax_C: +85°C; Number Of Channels: 2; Input Bias Current: -0.0035uA; Max Supply Voltage: 36V; Standoff Height: 0.05mm; Output Current Per Channel: 21mA; Input Offset Voltage: 0.37mV; Response Time: 1us; TJmax_C: +150°C; SizeZ_mm: 1.1mm; AEC Qualified: No
U3 = CMP-0092668-1: 120-V Half-Bridge Driver with Negative Voltage Handling and Low Switching Losses; Manufacturer: Texas Instruments; AEC Qualified: No; Min Supply Voltage: 5.5V; Propagation Delay: 16ns; Turn On Delay Time: 1ns; Number Of Outputs: 2; Fall Time: 10ns; Standoff Height: 0mm; TJmax_C: +140°C; Max Supply Voltage: 16V; SizeZ_mm: 1mm; Rise Time: 12ns; Nominal Supply Current: 0.3-2.2mA

## Sheet TIDA-010086E5_BiasPower.SchDoc
size 431 x 279 mm; Date: Not shown in title block; ApprovedBy: Not shown in title block; CheckedBy: Not shown in title block; Author: Not shown in title block; CompanyName: Not shown in title block; DrawnBy: Battery test; Engineer: Not shown in title block; Organization: Not shown in title block; Address1: Not shown in title block; Address2: Not shown in title block; Address3: Not shown in title block; Address4: Not shown in title block; DocumentNumber: 7; Revision: Use project parameter SCH_Rev; SheetNumber: 7; SheetTotal: 8; PageSetup: Record=PageOptions¦CenterHorizontal=True¦CenterVertical=True¦PrintScale=1.00¦XCorrection=1.00¦YCorrection=1.00¦PrintKind=0¦BorderSize=5000000¦LeftOffset=0¦BottomOffset=0¦Orientation=2¦PaperLength=1000¦PaperWidth=1000¦Scale=100¦PaperSource=15¦PrintQuality=600¦MediaType=1¦DitherType=10¦PaperKind=Letter¦PrintScaleMode=1
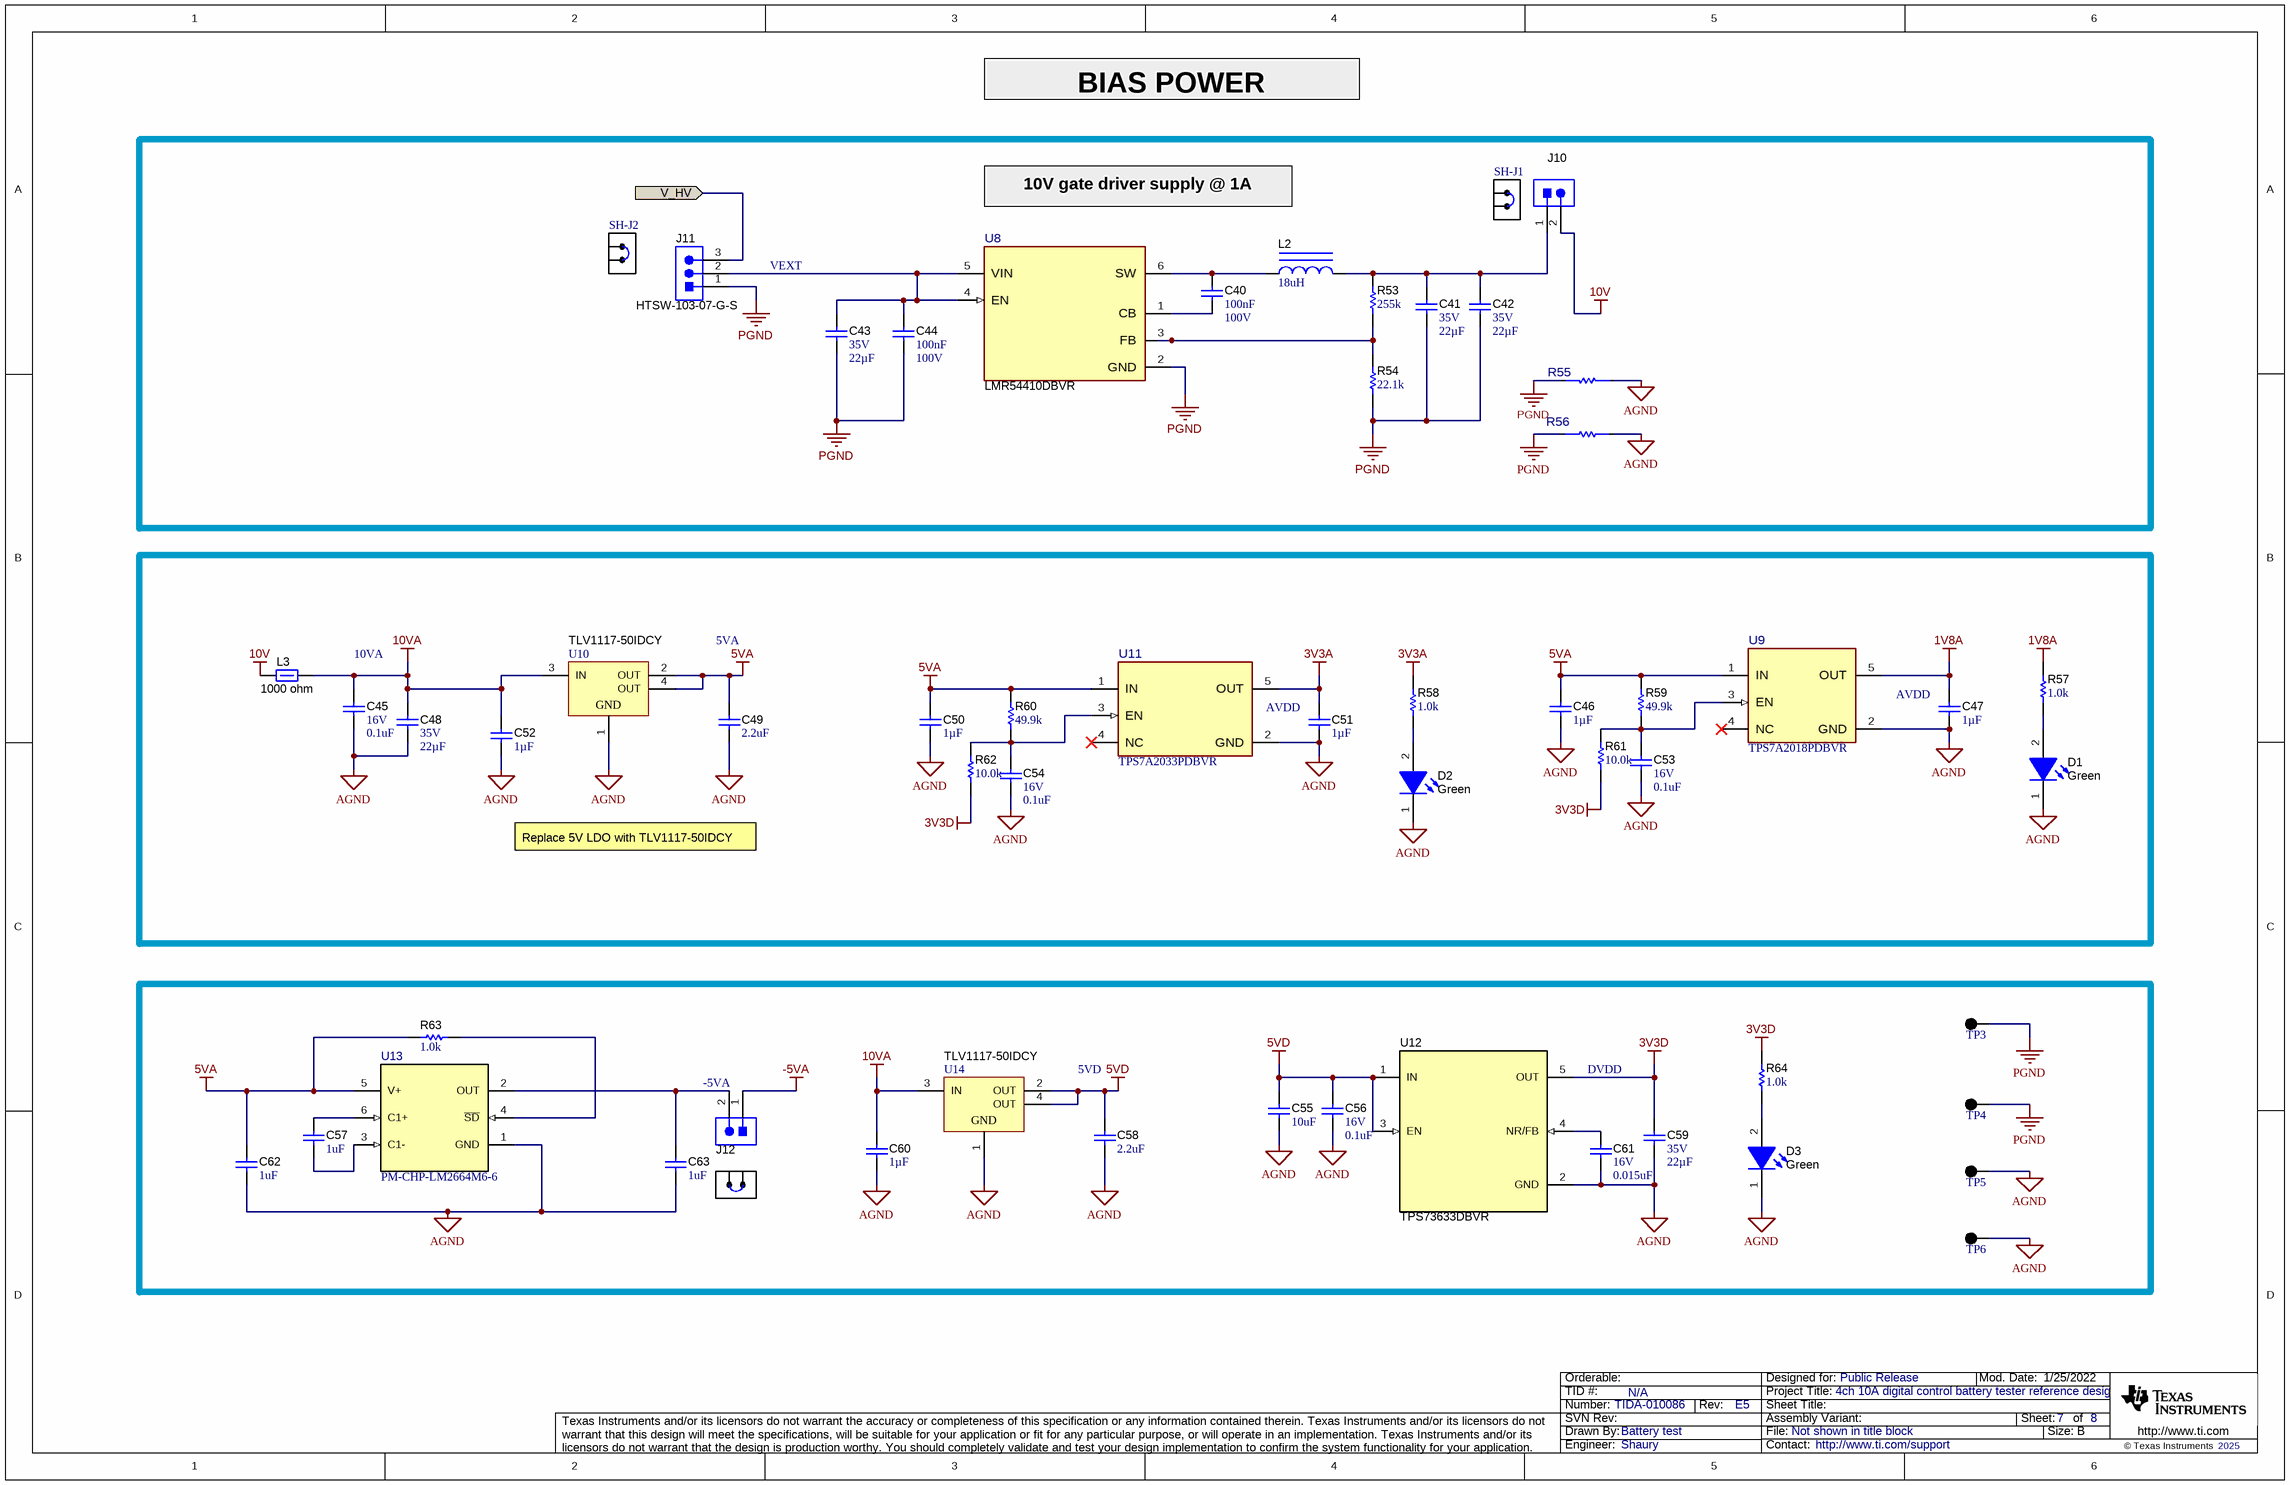
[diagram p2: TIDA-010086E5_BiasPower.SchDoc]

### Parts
C40  Cap_F: 100nF  VDC_V: 100V  [0603]  (hidden comment: GRM188R72A104KA35D)
C41  VDC_V: 35V  ValueDisplayed: 22µF  [1210]  (hidden comment: GMK325BJ226MM-P)
C42  VDC_V: 35V  ValueDisplayed: 22µF  [1210]  (hidden comment: GMK325BJ226MM-P)
C43  VDC_V: 35V  ValueDisplayed: 22µF  [1210]  (hidden comment: GMK325BJ226MM-P)
C44  Cap_F: 100nF  VDC_V: 100V  [0603]  (hidden comment: GRM188R72A104KA35D)
C45  VDC_V: 16V  ValueDisplayed: 0.1uF  [0402]  (hidden comment: GRM155R61C104KA88D)
C46  ValueDisplayed: 1µF  [0603S]  (hidden comment: CGA3E1X7R1E105K080AC)
C47  ValueDisplayed: 1µF  [0603S]  (hidden comment: CGA3E1X7R1E105K080AC)
C48  VDC_V: 35V  ValueDisplayed: 22µF  [1210]  (hidden comment: GMK325BJ226MM-P)
C49  ValueDisplayed: 2.2uF  [0603S]  (hidden comment: F381A225MMA)
C50  ValueDisplayed: 1µF  [0603S]  (hidden comment: CGA3E1X7R1E105K080AC)
C51  ValueDisplayed: 1µF  [0603S]  (hidden comment: CGA3E1X7R1E105K080AC)
C52  ValueDisplayed: 1µF  [0603S]  (hidden comment: CGA3E1X7R1E105K080AC)
C53  VDC_V: 16V  ValueDisplayed: 0.1uF  [0402]  (hidden comment: GRM155R61C104KA88D)
C54  VDC_V: 16V  ValueDisplayed: 0.1uF  [0402]  (hidden comment: GRM155R61C104KA88D)
C55  ValueDisplayed: 10uF  [0603]  (hidden comment: GRM188R61E106MA73D)
C56  VDC_V: 16V  ValueDisplayed: 0.1uF  [0402]  (hidden comment: GRM155R61C104KA88D)
C57  ValueDisplayed: 1uF  [0805_HV]  (hidden comment: GRM21BR71H105KA12L)
C58  ValueDisplayed: 2.2uF  [0603S]  (hidden comment: F381A225MMA)
C59  VDC_V: 35V  ValueDisplayed: 22µF  [1210]  (hidden comment: GMK325BJ226MM-P)
C60  ValueDisplayed: 1µF  [0603S]  (hidden comment: CGA3E1X7R1E105K080AC)
C61  VDC_V: 16V  ValueDisplayed: 0.015uF  [0402]  (hidden comment: GRM155R71C153KA01D)
C62  ValueDisplayed: 1uF  [0805_HV]  (hidden comment: GRM21BR71H105KA12L)
C63  ValueDisplayed: 1uF  [0805_HV]  (hidden comment: GRM21BR71H105KA12L)
D1  value Green  [WL-SMCW_GREEN]  (hidden comment: 150060VS75000)
D2  value Green  [WL-SMCW_GREEN]  (hidden comment: 150060VS75000)
D3  value Green  [WL-SMCW_GREEN]  (hidden comment: 150060VS75000)
J10  HTSW-102-07-G-S  [Samtec_HTSW-102-07-G-S]  (value not drawn)
J11  HTSW-103-07-G-S  [Samtec_HTSW-103-07-G-S]
J12  HTSW-102-07-G-S  [Samtec_HTSW-102-07-G-S]  (value not drawn)
L2  ValueDisplayed: 18uH  [LPS5015]  (hidden comment: LPS5015-183MLB)
L3  value 1000 ohm  [1806_HighSpeed]  (hidden comment: BLM41PG102SN1L)
R53  ValueDisplayed: 255k  [0402]  (hidden comment: CRCW0402255KFKED)
R54  ValueDisplayed: 22.1k  [0402]  (hidden comment: CRCW040222K1FKED)
R55  CRCW12060000Z0EAC  [FP-CRCW12060000Z0EAC_1206-MFG]  (value not drawn)
R56  CRCW12060000Z0EAC  [FP-CRCW12060000Z0EAC_1206-MFG]  (value not drawn)
R57  ValueDisplayed: 1.0k  [0603]  (hidden comment: CRCW06031K00JNEA)
R58  ValueDisplayed: 1.0k  [0603]  (hidden comment: CRCW06031K00JNEA)
R59  ValueDisplayed: 49.9k  [0603]  (hidden comment: CRCW060349K9FKEA)
R60  ValueDisplayed: 49.9k  [0603]  (hidden comment: CRCW060349K9FKEA)
R61  ValueDisplayed: 10.0k  [0603]  (hidden comment: CRCW060310K0FKEA)
R62  ValueDisplayed: 10.0k  [0603]  (hidden comment: CRCW060310K0FKEA)
R63  ValueDisplayed: 1.0k  [0603]  (hidden comment: CRCW06031K00JNEA)
R64  ValueDisplayed: 1.0k  [0603]  (hidden comment: CRCW06031K00JNEA)
SH-J1  60900213421  [Wurth_60900213421]  (value not drawn)
SH-J2  60900213421  [Wurth_60900213421]  (value not drawn)
SH-J3  60900213421  [Wurth_60900213421]  (value not drawn)
TP3  5001  [Keystone5001]  (value not drawn)
TP4  5001  [Keystone5001]  (value not drawn)
TP5  5001  [Keystone5001]  (value not drawn)
TP6  5001  [Keystone5001]  (value not drawn)
U8  LMR54410DBVR  [DBV0006A-MFG]
U9  TPS7A2018PDBVR  [DBV0005A-MFG]
U10  PartNumber: TLV1117-50IDCY  [DCY0004A_N]  (hidden comment: TLV1117LV30DCYR)
U11  TPS7A2033PDBVR  [DBV0005A-MFG]
U12  TPS73633DBVR  [DBV0005A_N]
U13  PM-CHP-LM2664M6-6  [DBV0006A_M]
U14  PartNumber: TLV1117-50IDCY  [DCY0004A_N]  (hidden comment: TLV1117LV30DCYR)

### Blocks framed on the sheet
VEXT: C40-C44 J10 J11 L2 R53-R56 SH-J1 SH-J2 U8

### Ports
V_HV (in)

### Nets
1V8A: C47.1 R57.2 U9.5(OUT)
3V3A: C51.1 R58.2 U11.5(OUT)
3V3D: C59.1 R61.1 R62.1 R64.2 U12.5(OUT)
5VA: C46.1 C49.1 C50.1 C62.1 R59.1 R60.1 R63.2 U9.1(IN) U10.2(OUT) U10.4(OUT) U11.1(IN) U13.5(V+)
5VD: C55.1 C56.2 C58.1 U12.1(IN) U12.3(EN) U14.2(OUT) U14.4(OUT)
10V: J10.2 L3.1
10VA: C45.2 C48.1 C52.1 C60.1 L3.2 U10.3(IN) U14.3(IN)
-5VA: J12.1
AGND: C45.1 C46.2 C47.2 C48.2 C49.2 C50.2 C51.2 C52.2 C53.1 C54.1 C55.2 C56.1 C58.2 C59.2 C60.2 C61.2 C62.2 C63.2 D1.1(K) D2.1(K) D3.1(K) R55.1 R56.2 TP5.1 TP6.1 U9.2(GND) U10.1(GND) U11.2(GND) U12.2(GND) U13.1(GND) U14.1(GND)
PGND: C41.2 C42.2 C43.2 C44.2 J11.1 R54.1 R55.2 R56.1 TP3.1 TP4.1 U8.2(GND)
V_HV: J11.3 ; port V_HV
NetC40_1: C40.1 L2.1 U8.6(SW)
NetC40_2: C40.2 U8.1(CB)
NetC41_1: C41.1 C42.1 J10.1 L2.2 R53.2
NetC43_1: C43.1 C44.1 J11.2 U8.4(EN) U8.5(VIN)
NetC53_2: C53.2 R59.2 R61.2 U9.3(EN)
NetC54_2: C54.2 R60.2 R62.2 U11.3(EN)
NetC57_1: C57.1 U13.6(C1+)
NetC57_2: C57.2 U13.3(C1-)
NetC61_1: C61.1 U12.4(NR/FB)
NetC63_1: C63.1 J12.2 U13.2(OUT)
NetD1_2: D1.2(A) R57.1
NetD2_2: D2.2(A) R58.1
NetD3_2: D3.2(A) R64.1
NetR53_1: R53.1 R54.2 U8.3(FB)
NetR63_1: R63.1 U13.4(~{SD})

Not connected (* = marked no-connect by the designer): U9 4(NC)*; U11 4(NC)*

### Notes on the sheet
- BIAS POWER
- 10V gate driver supply @ 1A
- 10VA
- 5VA
- AVDD
- (near U11) AVDD
- Replace 5V LDO with TLV1117-50IDCY
- (near J12) -5VA
- 5VD
- (near U12) DVDD

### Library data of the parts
C40 C44 = CMP-0007469-4: as C6 on sheet TIDA-010086E5_PowerStage
C41-C43 C48 C59 = CMP-0085817-1: as C3 on sheet TIDA-010086E5_PowerStage
C45 C53 C54 C56 = CMP-0006591-2: as C22 on sheet TIDA-010086E5_PowerStage
C46 C47 C50-C52 C60 = CMP-0076705-3: CAP, CERM, 1 µF, 25 V,+/- 10%, X7R, AEC-Q200 Grade 1, 0603; Manufacturer: TDK; Polarized: N; Value: 1uF; U/M: EA; VDC_V: 25V; TaMin_C: -55°C; TaMax_C: 125°C; Cap_Case: 1.6x0.8x0.8mm; SizeAreaWB_mm2: 4.68; SizeArea_mm2: 1.28; AEC Qualified: Y; AEC Category: Q200; SizeZ_mm: 1.0; AEC Grade: 1; SizeY_mm: 0.8; SizeX_mm: 1.6
C49 = CMP-0076705-3: CAP TANT POLY 2.2UF 10V 0603; Manufacturer: KYOCERA AVX; Polarized: N; U/M: EA; Tolerance_%: 20%; ESR_ohm: 0.2; TempCo: X7R; TaMin_C: -55°C; TaMax_C: 125°C; Cap_Case: 1.6x0.8x0.8mm; SizeAreaWB_mm2: 4.68; SizeArea_mm2: 1.28; AEC Qualified: Y; AEC Category: Q200; SizeZ_mm: 1.0; AEC Grade: 1; SizeY_mm: 0.8; SizeX_mm: 1.6
C55 = CMP-0007344-5: CAP, CERM, 10 uF, 25 V, +/- 20%, X5R, 0603; Manufacturer: MuRata; Polarized: N; Value: 10uF; U/M: EA; Cap_F: 10µF; Value1: Unknown; VDC_V: 25V; TaMin_C: -55°C; TaMax_C: 85°C; SizeArea_mm2: 1.28; SizeAreaWB_mm2: 4.68; SizeX_mm: 1.6; SizeY_mm: 0.8; SizeZ_mm: 1; AEC Category: Q200
C57 C62 C63 = CMP-0008350-2: as C5 on sheet TIDA-010086E5_PowerStage
C58 = CMP-0076705-3: CAP TANT POLY 2.2UF 10V 0603; Manufacturer: KYOCERA AVX; Polarized: N; Value: 1uF; U/M: EA; Tolerance_%: 20%; ESR_ohm: 0.2; TempCo: X7R; TaMin_C: -55°C; TaMax_C: 125°C; Cap_Case: 1.6x0.8x0.8mm; SizeAreaWB_mm2: 4.68; SizeArea_mm2: 1.28; AEC Qualified: Y; AEC Category: Q200; SizeZ_mm: 1.0; AEC Grade: 1; SizeY_mm: 0.8; SizeX_mm: 1.6
C61 = CMP-0006644-2: as C20 on sheet TIDA-010086E5_PowerStage
D1-D3 = CMP-0002894-2: LED, Green, SMD; Manufacturer: Wurth Elektronik; Type: AlInGaP; Vf_V: 2V; Io_A: 20mA; Value1: W
J10 J12 = CMP-0075483-1: Header, 100mil, 2x1, Gold, TH; Manufacturer: Samtec; Green_REACh: Passed; CT: False; Green_Lifecycle: Active; CNHeader: True
J11 = CMP-0075484-1: as J5 on sheet TIDA-010086E5_TopLevel
L2 = CMP-0061372-2: Inductor, Shielded Drum Core, Ferrite, 18 uH, 0.8 A, 0.55 ohm, SMD; Manufacturer: Coilcraft; Isat: 0.8A @ 30% inductance drop; Irms: 0.83A @ 40C rise; Green_Lifecycle: Not Set; SizeAreaWB_mm2: 33.64; DCR_ohm: 0.55; Green_REACh: Incomplete; Value: 18uH; Imax_A: 800mA; SizeZ_mm: 1.4; SizeX_mm: 4.8; Value2: 0.8A; SizeArea_mm2: 23.04; Ind_H: 18µH; AEC Category: Q200
L3 = CMP-0003369-1: Ferrite Bead, 1000 ohm @ 100 MHz, 1.5 A, 1806; Manufacturer: MuRata; ZTyp@100MHz_Ohm: 1k; SizeAreaWB_mm2: 14.3; DCR_ohm: 0.09; Value1: 0.09 ohm; Imax_A: 1.5A; SizeZ_mm: 1.85; SizeX_mm: 4.5; SizeY_mm: 1.6; SizeArea_mm2: 7.2
R53 = CMP-0026199-2: RES, 255 k, 1%, 0.063 W, AEC-Q200 Grade 0, 0402; Manufacturer: Vishay-Dale; Power_W: 63mW; TempCo: 100 ppm/C; Value: 255k; EIA_Code: E96; SizeX_mm: 1; SizeY_mm: 0.5; SizeZ_mm: 0.6; Value2: 0.063W; AEC Qualified: Y; VDC_V: 50V; AEC Category: Q200; AEC Grade: 0
R54 = CMP-0026178-2: RES, 22.1 k, 1%, 0.063 W, AEC-Q200 Grade 0, 0402; Manufacturer: Vishay-Dale; Power_W: 63mW; TempCo: 100 ppm/C; Value_Code: 22k1; Value: 22.1k; EIA_Code: E96; SizeX_mm: 1; SizeY_mm: 0.5; SizeZ_mm: 0.6; Value2: 0.063W; AEC Qualified: Y; VDC_V: 50V; AEC Category: Q200; AEC Grade: 0
R55 R56 = CMP-0094724-1: Jumper 0.25W, 1/4W Chip Resistor 1206 (3216 Metric) - Thick Film; Manufacturer: Vishay; Value: 0; Power_W: 250mW; VDC_V: 200V; SizeZ_mm: 0.65mm; AEC Qualified: No
R57 R58 R63 R64 = CMP-0025729-4: as R14 on sheet TIDA-010086E5_PowerStage
R59 R60 = CMP-0022447-4: as R2 on sheet TIDA-010086E5_PowerStage
R61 R62 = CMP-0021998-4: as R12 on sheet TIDA-010086E5_PowerStage
SH-J1-SH-J3 = CMP-0003761-2: Shunt, 2.54mm, Gold, Black; Manufacturer: Wurth Elektronik
TP3-TP6 = CMP-0055138-2: Test Point, Miniature, Black, TH; Manufacturer: Keystone Electronics; ContactFinish: Silver; Green_Lifecycle: Active; Green_REACh: Passed; CNHeader: FALSE; CT: TRUE
U8 = CMP-0093105-2: Buck Converter, Adjustable, 4V-36V Input, 1-28V 1A Output, SOT23-6; Manufacturer: Texas Instruments; SizeZ_mm: 1.45mm; Max Supply Voltage: 36V; Standoff Height: 0mm; Min Supply Voltage: 4V; Number Of Outputs: 1; TJmax_C: +150°C; Nominal Supply Current: 80uA; Max Duty Cycle: 98%; CompType: IC; Switching Frequency: 700kHz; AEC Qualified: No; Output Type: AdjustableProgrammable; AEC Category: Q200
U9 = CMP-0095212-1: Linear Voltage Regulator IC Positive Fixed 1 Output 300mA SOT-23-5; Manufacturer: Texas Instruments; TJmax_C: +125°C; Max Supply Voltage: 6V; SizeZ_mm: 1.45mm; Accuracy Percentage: 1.5%; AEC Qualified: No; Standoff Height: 0mm; Output Voltage: 1.8V; Min Supply Voltage: 1.6V; Nominal Supply Current: 6.5-2000uA; Dropout Voltage: 690mV; Number Of Outputs: 1
U10 U14 = CMP-0036758-1: Single Output LDO, 1 A, Fixed 5 V Output, 2 to 5.5 V Input, 4-pin SOT-223 (DCY), -40 to 125 degC, Green (RoHS & no Sb/Br); Manufacturer: Texas Instruments; Vout Adj(Max)(V): 3; Iq(Typ)(mA): 0.05; Vin(Max)(V): 5.5; Accuracy(%): 2; SubFamily: Single Channel LDO; Vdo(Typ)(mV): 1200; Iout(Max)(A): 1
U11 = CMP-0092532-1: 300-mA, Ultra-Low-Noise, Low-IQ, High PSRR LDO; Manufacturer: Texas Instruments; TJmax_C: +125°C; Min Supply Voltage: 1.6V; SizeZ_mm: 1.45mm; Output Voltage: 3.3V; Number Of Outputs: 1; Nominal Supply Current: 6.5uA; AEC Qualified: No; Accuracy Percentage: 1.5%; Max Supply Voltage: 6V; Dropout Voltage: 145mV; Standoff Height: 0mm; Output Type: Fixed
U12 = CMP-0036866-2: Single Output Low Noise LDO, 400 mA, Fixed 3.3 V Output, 1.7 to 5.5 V Input, with Reverse Current Protection, 5-pin SOT-23 (DBV), -40 to 85 degC, Green (RoHS & no Sb/Br); Manufacturer: Texas Instruments; Alternate PartNumber: TPS73633DBVT; Vout Adj(Min)(V): 3.3; Rating: Catalog; Accuracy(%): 1; Iq(Typ)(mA): 0.3; Vin(Max)(V): 5.5; SubFamily: Single Channel LDO; Vdo(Typ)(mV): 75; Vin(Min)(V): 1.7; Iout(Max)(A): 0.4; AEC Category: Q200; AEC Qualified: N; CompType: IC; Green_Lifecycle: Active; Green_REACh: Passed; SizeAreaWB_mm2: 14.82; SizeArea_mm2: 8.12; SizeX_mm: 2.8; SizeY_mm: 2.9; SizeZ_mm: 1.45
U13 = CMP-0072146-1: Switched Capacitor Voltage Converter, 6-pin SOT-23; PartNumber: LM2664M6X/NOPB; Manufacturer: Texas Instruments; PackageTopMarking: S03A*XTT; PowerWise: N; CompType: Switch Caps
